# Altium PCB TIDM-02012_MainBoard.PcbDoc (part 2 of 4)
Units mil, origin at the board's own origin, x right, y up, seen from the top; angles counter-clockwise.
Board outline 6550 x 5100 mil, 4 copper layers (Top Layer, Layer 1, Layer 2, Bottom Layer), stack 81.2 mil thick; 300 components, 157 nets, 916 pads, 350 vias.
Unrouted connection lines stored in the file: 93.
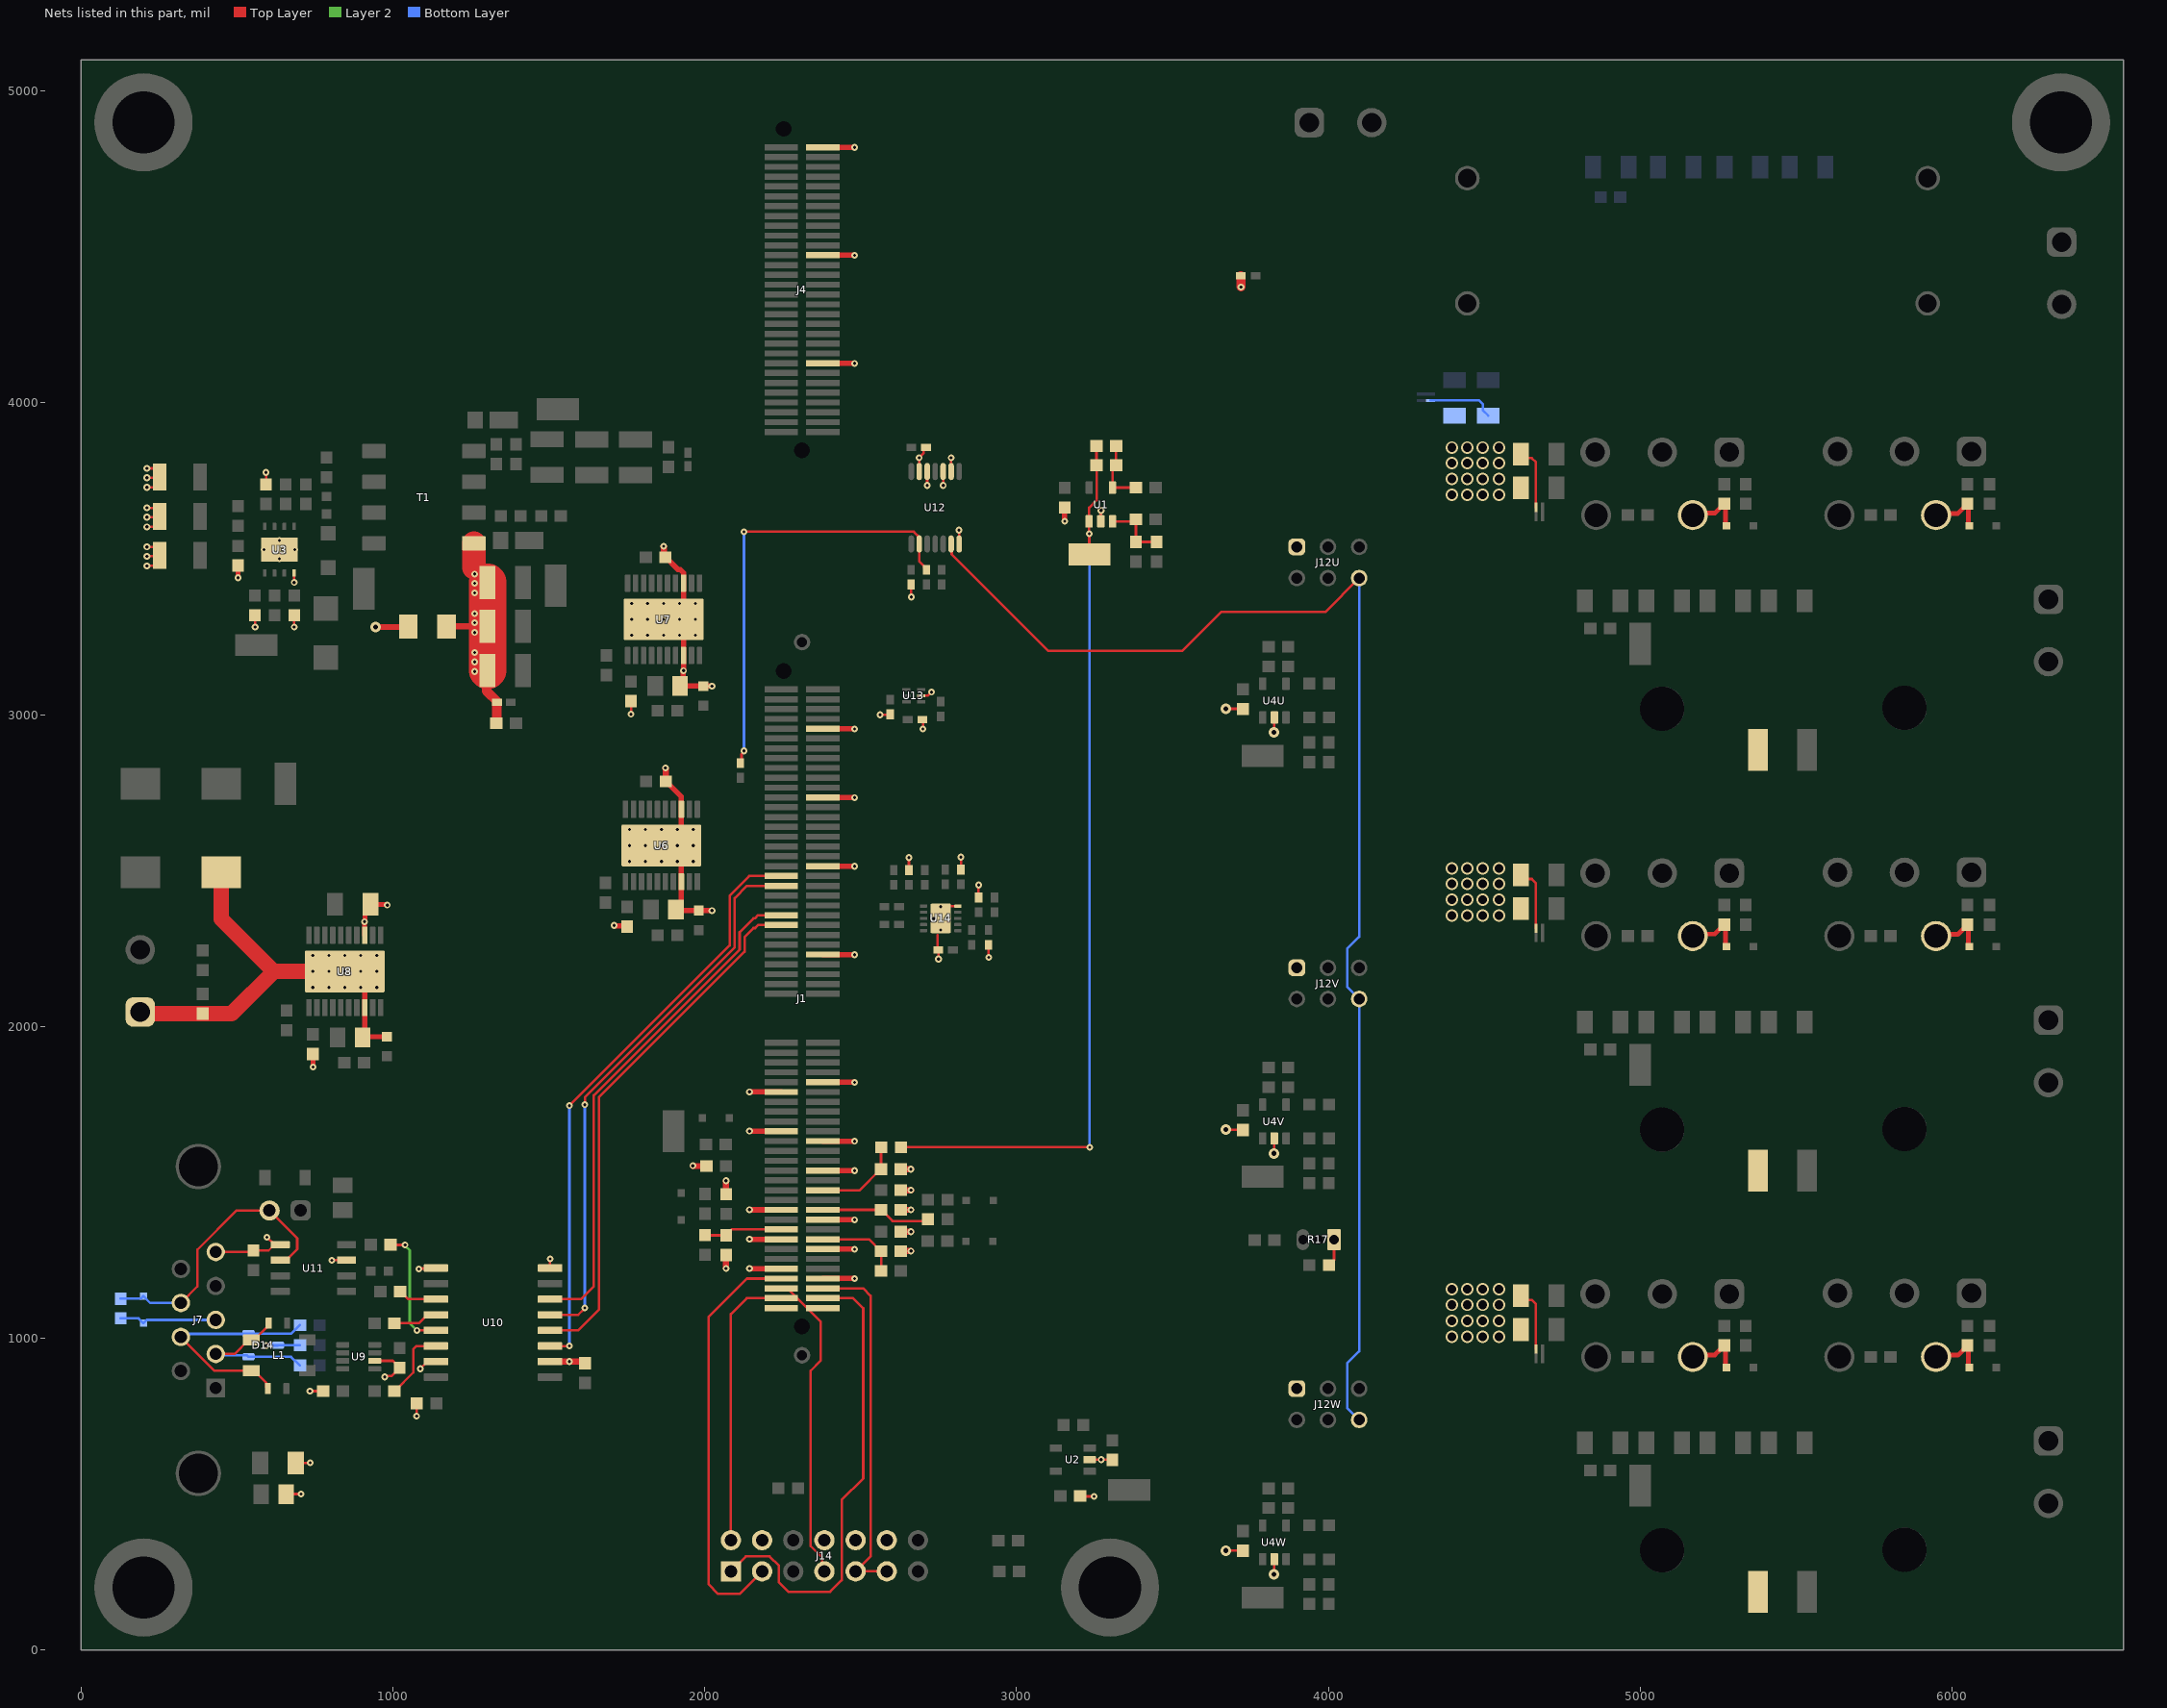
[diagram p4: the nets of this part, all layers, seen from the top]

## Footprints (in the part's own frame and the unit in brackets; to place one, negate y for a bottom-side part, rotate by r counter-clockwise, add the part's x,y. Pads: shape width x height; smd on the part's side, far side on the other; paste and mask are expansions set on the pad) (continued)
Wurth_691311500102 [mm] "Terminal Block, 2 Pos, 5.08mm, TH"
  rrect50% 2.4x2.4 hole 1.6: 1(-2.54,0)
  round 2.4 hole 1.6: 2(2.54,0)
  body extent -6.08,-3.8 6.08,4.7, height 12

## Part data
C1 C4 C18U C18V C18W C21U C21V C21W: library part CMP-0085572-1, "CAP, CERM, 47 pF, 100 V,+/- 5%, C0G/NP0, AEC-Q200 Grade 1, 0603", Cap_Case=0603, Manufacturer=Kemet, TempCo=C0G/NP0, Tolerance_%=5%, Value2=100V, ValueDisplayed=47pF
C2 C3 C11 C20U C20V C20W C28 C31 C42 C46: library part CMP-0006861-4, "CAP, CERM, 0.1 uF, 50 V, +/- 10%, X7R, 0603", Cap_Case=0603, Manufacturer=Kemet, Supplier Part Number 1=399-5089-1-ND, TempCo=X7R, Tolerance_%=10%, Value1=Unknown, Value2=50V, ValueDisplayed=0.1uF
C5 C19U C19V C19W: library part CMP-0085252-1, "CAP, CERM, 0.047 µF, 50 V,+/- 5%, X7R, 0603", Cap_Case=0603, Manufacturer=AVX, TempCo=X7R, Tolerance_%=5%, Value2=50V, ValueDisplayed=0.047µF
C6: library part CMP-0012359-3, "CAP, Film, 10 uF, 1300 V, +/- 10%, 0.0065 ohm, AEC-Q200 Grade 2, TH", Cap_Case=42x28x37mm, Manufacturer=TDK, Supplier Part Number 1=B32776G1106K-ND, Tolerance_%=10%, Value1="0.0065 ohm", Value2=1300V, ValueDisplayed=10uF
C7 C38U C38V C38W: library part CMP-0007221-4, "CAP, CERM, 470 pF, 50 V, +/- 5%, C0G/NP0, 0603", Cap_Case=0603, Manufacturer=MuRata, Supplier Part Number 1=490-1443-1-ND, TempCo=C0G/NP0, Tolerance_%=5%, Value1=Unknown, Value2=50V, ValueDisplayed=470pF
C8U C8V C8W: library part CMP-0009325-2, "CAP, CERM, 0.047 uF, 1000 V, +/- 10%, X7R, 1812", Cap_Case=1812, Manufacturer=Kemet, Supplier Part Number 1=399-6494-1-ND, TempCo=X7R, Tolerance_%=10%, Value1=Unknown, Value2=1000V, ValueDisplayed=0.047uF
C12 C32 C33: library part CMP-0007255-4, "CAP, CERM, 22 pF, 100 V, +/- 5%, C0G/NP0, 0603", Cap_Case=0603, Manufacturer=MuRata, Supplier Part Number 1=490-1335-1-ND, TempCo=C0G/NP0, Tolerance_%=5%, Value1=Unknown, Value2=100V, ValueDisplayed=22pF
C13 C14 C37: library part CMP-0009164-2, "CAP, CERM, 10 uF, 50 V, +/- 10%, X7S, AEC-Q200 Grade 1, 1210", Cap_Case=1210_280, Manufacturer=TDK, Supplier Part Number 1=445-7004-1-ND, TempCo=X7S, Tolerance_%=10%, Value1="0.002827 ohm", Value2=50V, ValueDisplayed=10uF
C15 C16 C17 C23 C24 C29: library part CMP-0080552-1, "CAP, CERM, 22 µF, 25 V,+/- 10%, X7R, AEC-Q200 Grade 1, 1210", Cap_Case=1210, Manufacturer="Taiyo Yuden", Supplier Part Number 1=587-5949-1-ND, TempCo=X7R, Tolerance_%=10%, Value2=25V, ValueDisplayed=22µF
C22 C30: library part CMP-0079602-1, "CAP, CERM, 0.1 µF, 50 V,+/- 10%, X7R, AEC-Q200 Grade 1, 0603", Cap_Case=0603, Manufacturer=Kemet, Supplier Part Number 1=399-6856-1-ND, TempCo=X7R, Tolerance_%=10%, Value2=50V, ValueDisplayed=0.1µF
C25 C40: library part CMP-0082113-1, "CAP, CERM, 1 µF, 25 V,+/- 20%, X7R, AEC-Q200 Grade 1, 0603", Cap_Case=0603, Manufacturer=TDK, Supplier Part Number 1=445-12548-2-ND, TempCo=X7R, Tolerance_%=20%, Value2=25V, ValueDisplayed=1µF
C26 C41 C45: library part CMP-0008003-2, "CAP, CERM, 10 uF, 16 V, +/- 20%, X7R, 0805", Cap_Case=0805, Manufacturer="Taiyo Yuden", Supplier Part Number 1=587-3319-1-ND, TempCo=X7R, Tolerance_%=20%, Value1=Unknown, Value2=16V, ValueDisplayed=10uF
C27 C34: library part CMP-0007079-4, "CAP, CERM, 0.047 uF, 50 V, +/- 10%, X7R, AEC-Q200 Grade 1, 0603", Cap_Case=0603, Manufacturer=TDK, Supplier Part Number 1=445-5664-1-ND, TempCo=X7R, Tolerance_%=10%, Value1="0.049007 ohm", Value2=50V, ValueDisplayed=0.047uF
C35: library part CMP-0008572-2, "CAP, CERM, 1000 pF, 2000 V, +/- 10%, X7R, 1206_190", Cap_Case=1206, Manufacturer="Johanson Technology", TempCo=X7R, Tolerance_%=10%, Value1=Unknown, Value2=2000V, ValueDisplayed=1000pF
C36: library part CMP-0007141-3, "CAP, CERM, 0.047 uF, 25 V, +/- 10%, X7R, AEC-Q200 Grade 1, 0603", Cap_Case=0603, Manufacturer=MuRata, Supplier Part Number 1=490-8018-1-ND, TempCo=X7R, Tolerance_%=10%, Value1=Unknown, Value2=25V, ValueDisplayed=0.047uF
C39U C39V C39W C43: library part CMP-0007197-4, "CAP, CERM, 220 pF, 50 V, +/- 5%, C0G/NP0, 0603", Cap_Case=0603, Manufacturer=MuRata, Supplier Part Number 1=490-1435-1-ND, TempCo=C0G/NP0, Tolerance_%=5%, Value1=Unknown, Value2=50V, ValueDisplayed=220pF
C44: library part CMP-0008821-2, "CAP, CERM, 10 uF, 35 V, +/- 10%, X7R, 1206", Cap_Case=1206, Manufacturer="Taiyo Yuden", Supplier Part Number 1=587-3007-1-ND, TempCo=X7R, Tolerance_%=10%, Value1=Unknown, Value2=35V, ValueDisplayed=10uF
C47 C49 C50 C51: library part CMP-0006857-4, "CAP, CERM, 0.1 uF, 16 V, +/- 5%, X7R, 0603", Cap_Case=0603, Manufacturer=Kemet, Supplier Part Number 1=399-1097-1-ND, TempCo=X7R, Tolerance_%=5%, Value1=Unknown, Value2=16V, ValueDisplayed=0.1uF
C48: library part CMP-0007088-4, "CAP, CERM, 4700 pF, 100 V, +/- 10%, X7R, AEC-Q200 Grade 1, 0603", Cap_Case=0603, Manufacturer=TDK, Supplier Part Number 1=445-5810-1-ND, TempCo=X7R, Tolerance_%=10%, Value1="0.469862 ohm", Value2=100V, ValueDisplayed=4700pF
C52: library part CMP-0006777-4, "CAP, CERM, 220 pF, 50 V, +/- 5%, C0G/NP0, 0603", Cap_Case=0603, Manufacturer=AVX, Supplier Part Number 1=478-1179-1-ND, TempCo=C0G/NP0, Tolerance_%=5%, Value1="0.083 ohm", Value2=50V, ValueDisplayed=220pF
C53: library part CMP-0008484-2, "CAP, CERM, 0.01 uF, 100 V, +/- 5%, X7R, 1206", Cap_Case=1206, Manufacturer=AVX, Supplier Part Number 1=478-3783-1-ND, TempCo=X7R, Tolerance_%=5%, Value1="0.119 ohm", Value2=100V, ValueDisplayed=0.01uF
C54 C55 C56 C57 C58: library part CMP-0080702-1, "CAP, CERM, 0.1 µF, 16 V,+/- 5%, X7R, AEC-Q200 Grade 1, 0402", Cap_Case=0402, Manufacturer=MuRata, Supplier Part Number 1=490-16433-1-ND, TempCo=X7R, Tolerance_%=5%, Value2=16V, ValueDisplayed=0.1µF
C59: library part CMP-0080610-1, "CAP, CERM, 0.1 µF, 25 V,+/- 10%, X7R, AEC-Q200 Grade 1, 0402", Cap_Case=0402, Manufacturer=TDK, Supplier Part Number 1=445-6902-1-ND, TempCo=X7R, Tolerance_%=10%, Value2=25V, ValueDisplayed=0.1µF
D1 D7U D7V D7W: library part CMP-0028792-2, "Diode, Schottky, 40 V, 0.52 A, AEC-Q101, SOD-323", Manufacturer="Diodes Inc.", Value1=0.52A, Value2=V
D2U D2V D2W D5U D5V D5W: library part CMP-0028748-2, "Diode, Schottky, 40 V, 0.5 A, SOD-323", Manufacturer=Toshiba, Value1=0.5A, Value2=0.6V
D3 D10: library part CMP-0028825-2, "Diode, Schottky, 60 V, 3 A, AEC-Q101, SOD-123HE", Manufacturer="Fairchild Semiconductor", Value1=3A, Value2=0.65V
D4: library part CMP-0005882-5, "Diode, Zener, 18 V, 300 mW, SOD-523", Manufacturer="Diodes Inc.", Power_W=300mW, Value1=0.3W
D6: library part CMP-0005514-4, "Diode, Zener, 27 V, 3 W, SMA", Manufacturer="Micro Commercial Components", Power_W=3W
D8: library part CMP-0005904-4, "Diode, Zener, 8.2 V, 300 mW, SOD-523", Manufacturer="Diodes Inc.", Power_W=300mW, Value1=0.3W
D9: library part CMP-0077075-2, "Diode, Schottky, 100 V, 3 A, AEC-Q101, SMC", Manufacturer=Vishay-Siliconix, Value1=3A, Value2=0.8V
D11: library part CMP-0005729-4, "Diode, TVS, Uni, 26 V, 42.1 Vc, AEC-Q101, SMC", Manufacturer=Littelfuse, Value1=3000W
D12 D13 D17: library part CMP-0002892-3, "LED, Yellow, SMD", Color=yellow, Manufacturer="Wurth Elektronik", Value1=W, Value2=2V
D14: library part CMP-0005919-3, "Diode, TVS, Bi, 24 V, SOT-23", Manufacturer="ON Semiconductor", Value1=350W
D15: library part CMP-0076974-2, "Diode, Switching, 100 V, 0.15 A, SOD-123", Manufacturer="Micro Commercial Components", Value1=0.15A, Value2=1.25V
D16: library part CMP-0005821-3, "Diode, TVS, Bi, 15 V, SOD-323", Manufacturer="NXP Semiconductor", Value1=160W
D18: library part CMP-0085903-1, "Diode, Schottky, 60 V, 3 A, AEC-Q101, SOD-123W", Manufacturer=Nexperia, Value1=3A, Value2=0.62V
H1 H2 H3 H4: library part CMP-0003617-1, "Machine Screw, Round, #4-40 x 1/4, Nylon, Philips panhead", Manufacturer="B&F Fastener Supply", Supplier Part Number 1=H542-ND
H5 H6 H7 H8: library part CMP-0003610-1, "Standoff, Hex, 0.5\"L #4-40 Nylon", Manufacturer=Keystone, Supplier Part Number 1=36-1902C-ND
"High Voltage1" "High Voltage2": library part CMP-0074835-1, "IEC 61010-1 High Voltage Warning"
J1: library part CMP-0003814-2, "C2000 controlCARD-120HSEC connector, SMT", Manufacturer=Samtec
J2 J3 J5 J13U J13V J13W: library part CMP-0084907-1, "Terminal Block, 2 Pos, 5.08mm, Tin, TH", Color=Green, Current_A=20A, Manufacturer="Wurth Elektronik", Voltage_V=300V
J4: library part CMP-0003859-2, "C2000 controlCARD-180HSEC (60-pin addon) connector, SMT", Manufacturer=Samtec
J6: library part CMP-0075405-3, "Header, 100mil, 2x1, Gold, TH", Color=Black, Current_A=6.3A, Manufacturer=Samtec, Supplier Part Number 1=SAM1029-02-ND, Voltage_V=550V
J7: library part CMP-0054820-2, "Receptacle, D-Sub, 9 Position, R/A, TH", Color=Black, Current_A=3A, Manufacturer="Wurth Elektronik", Supplier Part Number 1=16T0655, Voltage_V=125V
J8U J8V J8W J9U J9V J9W J10U J10V J10W J11U J11V J11W: library part CMP-0055026-1, Manufacturer=Mill-Max, Supplier Part Number 1=0312-015153427100-ND
J12U J12V J12W: library part CMP-0082603-1, "Receptacle, 2.54mm, 3x2, Tin, TH", Color=Green, Manufacturer="TE Connectivity", Supplier Part Number 1=A106656-ND
J14: library part CMP-0054695-2, "Header (shrouded), 100 mil, 7x2, Gold, TH", Manufacturer="Sullins Connector Solutions", Supplier Part Number 1=S9170-ND
L1: library part CMP-0062430-2, "Inductor, Ferrite, 100 uH, 0.15 A, 2 ohm, SMD", Manufacturer=TDK, Supplier Part Number 1=445-3959-1-ND, Value1="2 ohm", Value2=0.15A, ValueDisplayed=100uH
LBL1: library part CMP-0003625-1, "Thermal Transfer Printable Labels, 0.650\" W x 0.200\" H - 10,000 per roll", Manufacturer=Brady, Supplier Part Number 1=97C5133
Logo1: library part CMP-0074838-1, "Texas Instrument Corporate Signature"
Logo2: library part CMP-0074844-1
Logo3: library part CMP-0074847-1, "FCC_disclaimer"
Logo4: library part CMP-0074769-1
NT1 NT2 NT3U NT3V NT3W NT4U NT4V NT4W: library part CMP-0078142-4, "Single point connection between nets.", Manufacturer=N/A
Q1U Q1V Q1W Q2U Q2V Q2W: library part CMP-0000526-4, "Transistor, IGBT, 1200 V, 50 A, TO-247", Manufacturer="Infineon Technologies", Value1="50 A"
R1 R2 R24U R24V R24W R25U R25V R25W: library part CMP-0018570-2, "RES, 0.01, 1%, 1 W, 1206", Manufacturer=Vishay-Dale, Power_W=1W, Supplier Part Number 1=WSLP-.01CT-ND, TempCo="75 ppm/C", Tolerance_%=1%, Value_Code=R010, ValueDisplayed=0.01
R3 R5 R10 R12 R14 R16U R16V R16W R23U R23V R23W R29U R29V R29W R33U R33V R33W R41 R46 R48 R57: library part CMP-0022746-5, "RES, 10.0 k, 1%, 0.1 W, 0603", Manufacturer=Yageo, Power_W=100mW, Supplier Part Number 1=311-10.0KHRCT-ND, TempCo="100 ppm/C", Tolerance_%=1%, Value2=0.1W, Value_Code=10k0, ValueDisplayed=10.0k
R4 R9 R31U R31V R31W R32U R32V R32W: library part CMP-0022895-5, "RES, 1.00 k, 1%, 0.1 W, 0603", Manufacturer=Yageo, Power_W=100mW, Supplier Part Number 1=311-1.00KHRCT-ND, TempCo="100 ppm/C", Tolerance_%=1%, Value2=0.1W, Value_Code=1k00, ValueDisplayed=1.00k
R6 R7 R8 R26U R26V R26W R27U R27V R27W R28U R28V R28W: library part CMP-0017631-3, "RES, 499 k, 1%, 0.25 W, AEC-Q200 Grade 0, 1206", Manufacturer=Panasonic, Power_W=250mW, Supplier Part Number 1=P499KFCT-ND, TempCo="100 ppm/C", Tolerance_%=1%, Value2=0.25W, Value_Code=499k
R11 R30U R30V R30W: library part CMP-0017634-3, "RES, 5.11 k, 1%, 0.25 W, AEC-Q200 Grade 0, 1206", Manufacturer=Panasonic, Power_W=250mW, Supplier Part Number 1=P5.11KFCT-ND, TempCo="100 ppm/C", Tolerance_%=1%, Value2=0.25W, Value_Code=5k11, ValueDisplayed=5.11k
R13U R13V R13W R20U R20V R20W: library part CMP-0022170-4, "RES, 1.00, 1%, 0.1 W, AEC-Q200 Grade 0, 0603", Manufacturer=Vishay-Dale, Power_W=100mW, Supplier Part Number 1=52K8059, TempCo="100 ppm/C", Tolerance_%=1%, Value2=0.1W, Value_Code=1R00, ValueDisplayed=1.00
R15U R15V R15W R22U R22V R22W: library part CMP-0023206-5, "RES, 5.11, 1%, 0.1 W, 0603", Manufacturer=Yageo, Power_W=100mW, Supplier Part Number 1=311-5.11HRCT-ND, TempCo="200 ppm/C", Tolerance_%=1%, Value2=0.1W, Value_Code=5R11, ValueDisplayed=5.11
R17: library part CMP-0088739-1, "PTC Thermistor 10 kOhms TO-226-2, TO-92-2 (TO-226AC) Short Body", Digikey Part Number=296-TMP6131QLPGMQ1CT-ND, Manufacturer="Texas Instruments", Mouser Part Number=595-TMP6131QLPGMQ1, Operating Temperature Range="-40°C to +125°C", TempCo=6400ppm/°C, Tolerance_%=1%
R18 R21: library part CMP-0084243-1, "RES, 100, 1%, 0.25 W, AEC-Q200 Grade 0, 0603", Manufacturer=Vishay-Dale, Power_W=250mW, TempCo="100 ppm/C", Tolerance_%=1%, Value2=0.25W, Value_Code=100R, ValueDisplayed=100
R19: library part CMP-0021991-4, "RES, 100, 1%, 0.1 W, AEC-Q200 Grade 0, 0603", Manufacturer=Vishay-Dale, Power_W=100mW, Supplier Part Number 1=541-100HCT-ND, TempCo="100 ppm/C", Tolerance_%=1%, Value2=0.1W, Value_Code=100R, ValueDisplayed=100
R34: library part CMP-0022841-5, "RES, 17.8 k, 1%, 0.1 W, 0603", Manufacturer=Yageo, Power_W=100mW, Supplier Part Number 1=311-17.8KHRCT-ND, TempCo="100 ppm/C", Tolerance_%=1%, Value2=0.1W, Value_Code=17k8, ValueDisplayed=17.8k
R35: library part CMP-0023028-4, "RES, 324 k, 1%, 0.1 W, 0603", Manufacturer=Yageo, Power_W=100mW, Supplier Part Number 1=311-324KHRCT-ND, TempCo="100 ppm/C", Tolerance_%=1%, Value2=0.1W, Value_Code=324k
R36: library part CMP-0023216-5, "RES, 61.9 k, 1%, 0.1 W, 0603", Manufacturer=Yageo, Power_W=100mW, Supplier Part Number 1=311-61.9KHRCT-ND, TempCo="100 ppm/C", Tolerance_%=1%, Value2=0.1W, Value_Code=61k9, ValueDisplayed=61.9k
R37: library part CMP-0023077-5, "RES, 3.09 k, 1%, 0.1 W, 0603", Manufacturer=Yageo, Power_W=100mW, Supplier Part Number 1=311-3.09KHRCT-ND, TempCo="100 ppm/C", Tolerance_%=1%, Value2=0.1W, Value_Code=3k09, ValueDisplayed=3.09k
R38: library part CMP-0023202-5, "RES, 5.62 k, 1%, 0.1 W, 0603", Manufacturer=Yageo, Power_W=100mW, Supplier Part Number 1=311-5.62KHRCT-ND, TempCo="100 ppm/C", Tolerance_%=1%, Value2=0.1W, Value_Code=5k62, ValueDisplayed=5.62k
R39: library part CMP-0022030-4, "RES, 12.1 k, 1%, 0.1 W, AEC-Q200 Grade 0, 0603", Manufacturer=Vishay-Dale, Power_W=100mW, Supplier Part Number 1=541-12.1KHCT-ND, TempCo="100 ppm/C", Tolerance_%=1%, Value2=0.1W, Value_Code=12k1, ValueDisplayed=12.1k
R40 R43U R43V R43W: library part CMP-0023168-5, "RES, 51.1, 1%, 0.1 W, 0603", Manufacturer=Yageo, Power_W=100mW, Supplier Part Number 1=311-51.1HRCT-ND, TempCo="100 ppm/C", Tolerance_%=1%, Value2=0.1W, Value_Code=51R1, ValueDisplayed=51.1
R42 R47 R74: library part CMP-0023013-5, "RES, 300, 1%, 0.1 W, 0603", Manufacturer=Yageo, Power_W=100mW, Supplier Part Number 1=311-300HRCT-ND, TempCo="100 ppm/C", Tolerance_%=1%, Value2=0.1W, Value_Code=300R, ValueDisplayed=300
R44 R64 R66 R67 R73 R79: library part CMP-0026992-3, "RES, 0, 5%, 0.1 W, AEC-Q200 Grade 0, 0402", Manufacturer=Panasonic, Power_W=100mW, Supplier Part Number 1=P0.0JCT-ND, TempCo="600 ppm/C", Tolerance_%=5%, Value2=0.1W, Value_Code=0000, ValueDisplayed=0
R45U R45V R45W R75: library part CMP-0022928-4, "RES, 22.0, 1%, 0.1 W, 0603", Manufacturer=Yageo, Power_W=100mW, Supplier Part Number 1=311-22.0HRCT-ND, TempCo="100 ppm/C", Tolerance_%=1%, Value2=0.1W, Value_Code=22R0, ValueDisplayed=22.0
R49 R54: library part CMP-0093667-1, "CRCW Thick Film Commodity Chip Resistor Jumper 0603 Size 0 Ohm 0.1 W 2-Pin SMD Paper T/R", Digikey Part Number=541-4013-1-ND, Manufacturer=Vishay, Mouser Part Number=71-CRCW06030000Z0EBC, Operating Temperature Range="-55°C to +155°C", Power_W=100mW
R50 R52: library part CMP-0023213-5, "RES, 60.4, 1%, 0.1 W, 0603", Manufacturer=Yageo, Power_W=100mW, Supplier Part Number 1=311-60.4HRCT-ND, TempCo="100 ppm/C", Tolerance_%=1%, Value2=0.1W, Value_Code=60R4, ValueDisplayed=60.4
R51 R53 R58 R59: library part CMP-0022926-4, "RES, 22.1, 1%, 0.1 W, 0603", Manufacturer=Yageo, Power_W=100mW, Supplier Part Number 1=311-22.1HRCT-ND, TempCo="100 ppm/C", Tolerance_%=1%, Value2=0.1W, Value_Code=22R1, ValueDisplayed=22.1
R55: library part CMP-0023343-3, "RES, 0, 1%, 0.1 W, AEC-Q200 Grade 0, 0603", Manufacturer="Stackpole Electronics Inc", Power_W=100mW, Supplier Part Number 1=RMCF0603ZT0R00CT-ND, TempCo=ppm/C, Tolerance_%=1%, Value2=0.1W, Value_Code=0
R56: library part CMP-0021519-3, "RES, 1.00 k, 1%, 0.125 W, AEC-Q200 Grade 0, 0805", Manufacturer=Panasonic, Power_W=125mW, Supplier Part Number 1=P1.00KCCT-ND, TempCo="100 ppm/C", Tolerance_%=1%, Value2=0.125W, Value_Code=1k00, ValueDisplayed=1.00k
R60: library part CMP-0021522-3, "RES, 1.00 M, 1%, 0.125 W, AEC-Q200 Grade 0, 0805", Manufacturer=Panasonic, Power_W=125mW, Supplier Part Number 1=P1.00MCCT-ND, TempCo="100 ppm/C", Tolerance_%=1%, Value2=0.125W, Value_Code=1M00, ValueDisplayed=1.00M
R61 R62 R63 R65 R68 R69 R70 R71 R72: library part CMP-0078779-1, "RES, 10.0 k, 1%, 0.2 W, AEC-Q200 Grade 0, 0402", Manufacturer=Panasonic, Power_W=200mW, Supplier Part Number 1=P17230CT-ND, TempCo="100 ppm/C", Tolerance_%=1%, Value2=0.2W, Value_Code=10k0, ValueDisplayed=10.0k
R76: library part CMP-0022679-3, "RES, 100, 1%, 0.1 W, AEC-Q200 Grade 0, 0603", Manufacturer=Panasonic, Power_W=100mW, Supplier Part Number 1=P100HCT-ND, TempCo="100 ppm/C", Tolerance_%=1%, Value2=0.1W, Value_Code=100R, ValueDisplayed=100
R77 R78: library part CMP-0023153-5, "RES, 4.70 k, 1%, 0.1 W, 0603", Manufacturer=Yageo, Power_W=100mW, Supplier Part Number 1=311-4.70KHRCT-ND, TempCo="100 ppm/C", Tolerance_%=1%, Value2=0.1W, Value_Code=4k70, ValueDisplayed=4.70k
T1: library part CMP-0094165-1, "Bobbin Packages EP7 8-Terminal, SMT, Horizonta", Frequency_Fixed=350kHz, Manufacturer="Wurth Electronics", Operating Temperature Range="-40°C to +125°C"
TP1 TP2 TP3 TP4U TP4V TP4W TP5U TP5V TP5W TP7 TP8 TP10: library part CMP-0055152-1, "Test Point, Miniature, SMT", Manufacturer=Keystone, Supplier Part Number 1=36-5015TR-ND
TP6 TP9: library part CMP-0055152-1, "Test Point, Miniature, SMT", Manufacturer=Keystone, PartNumber=5015, Supplier Part Number 1=36-5015TR-ND
U1 U4U U4V U4W: library part CMP-0861047-2, "50-MHz, Low-Power, Gain of 6-V/V Stable, Rail-to-Rail Output CMOS Operational Amplifier, DBV0005A (SOT-23-5)", Alternate Manufacturer="Texas Instruments"
U2: library part CMP-0073534-1, "3-MHz, Low-Power, Internal EMI Filter, RRIO, Operational Amplifier, DBV0005A (SOT-23-5)", Alternate Manufacturer="Texas Instruments", Alternate PartNumber=TLV314QDBVTQ1
U3: library part CMP-0860959-2, "42-VIN PSR Flyback DC/DC Converter with 65-V, 4-A Integrated MOSFET, NGU0008C (WSON-8)", Alternate Manufacturer="Texas Instruments"
U6: library part CMP-0085806-1, "Automotive 450mA High-Voltage Ultra-Low-Iq Low-Dropout Regulator, PWP0020D (HTSSOP-20)", Alternate Manufacturer="Texas Instruments", Operating Temperature Range="-40 to 125 C", Rating=Automotive
U7 U8: library part CMP-0085807-1, "Automotive 450mA High-Voltage Ultra-Low-Iq Low-Dropout Regulator, PWP0020D (HTSSOP-20)", Alternate Manufacturer="Texas Instruments", Operating Temperature Range="-40 to 125 C", Rating=Automotive
U9: library part CMP-0089901-1, "Automotive High Speed CAN Transceiver", Manufacturer="Texas Instruments", Max Supply Voltage=5.5V, Min Supply Voltage=4.5V, Nominal Supply Current=5-180mA, Operating Temperature Range="-40°C to +150°C"
U10: library part CMP-0093723-1, "General-Purpose Reinforced Quad-Channel Automotive Digital Isolators with Robust EMC", Digikey Part Number=296-ISO6742QDWRQ1CT-ND, Manufacturer="Texas Instruments", Max Supply Voltage=5.5V, Min Supply Voltage=1.71V, Mouser Part Number=595-ISO6742QDWRQ1, Operating Temperature Range="-40°C to +125°C"
U11: library part CMP-0091357-1, "Fault-Protected LIN Transceiver with Inhibit and Wake", Manufacturer="Texas Instruments", Max Supply Voltage=36V, Min Supply Voltage=4.5V, Nominal Supply Current=300-1200uA, Operating Temperature Range="-40°C to +125°C"
U12: library part CMP-0054468-2, "Automotive Catalog Dual 4-Input Positive-AND Gates, PW0014A, LARGE T&R", F @ Nom Voltage(Max)(Mhz)=70, Generic Part Number=SN74HC21-Q1, ICC @ Nom Voltage(Max)(mA)=0.02, Manufacturer="Texas Instruments", Operating Temperature Range(C)="-40 to 125", Rating=Automotive, tpd @ Nom Voltage(Max)(ns)=140, Voltage(Nom)(V)=5
U13: library part CMP-0750051-1, "Overvoltage and Undervoltage Reset IC With Time Delay and Manual Reset, DSE0006A (WSON-6)", Alternate Manufacturer="Texas Instruments"
U14: library part CMP-0081428-2, "Automotive Precision Voltage Supervisor With Programmable Window Watchdog Timer, DRC0010R (VSON-10)", Alternate Manufacturer="Texas Instruments", Operating Temperature Range="-40 to 125 C", Rating=Automotive
ZZ1: library part CMP-0003616-3
ZZ2: library part CMP-0077236-1
ZZ3: library part CMP-0077237-1
ZZ4: library part CMP-0077238-1

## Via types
v1: diameter 22, hole 10, Top Layer to Bottom Layer, tented both sides, 245 vias
v2: diameter 40, hole 28, Top Layer to Bottom Layer, tented both sides, 60 vias
v3: diameter 34, hole 16, Top Layer to Bottom Layer, tented both sides, 22 vias
v4: diameter 22, hole 10, Top Layer to Bottom Layer, 9 vias
v5: diameter 50, hole 28, Top Layer to Bottom Layer, tented both sides, 9 vias
v6: diameter 40, hole 25, Top Layer to Bottom Layer, tented both sides, 5 vias

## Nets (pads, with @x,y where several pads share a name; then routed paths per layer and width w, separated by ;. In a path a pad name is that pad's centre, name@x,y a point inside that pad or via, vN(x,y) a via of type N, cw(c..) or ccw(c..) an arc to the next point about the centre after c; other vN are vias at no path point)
CAN_H: D14.2 J7.7 L1.4 R52.1 R54.2 | length 754.3
  Top Layer w8: J7.7@320,1003.95 320,1002.5 426.5,896 L1.4@546,896 554.86,896 593.2,857.66 593.2,844.06 R54.2@599.04,838.21
  Bottom Layer w8: J7.7@320,1003.95 329.77,1013.71 535.71,1013.71 D14.2@537,1015 674.02,1015 701.02,1042 R52.1@702,1042
CAN_L: D14.1 J7.2 L1.3 R49.2 R50.2 | length 500.6
  Top Layer w8: J7.2@431.81,949.42 492.13,949.42 537.14,994.43 L1.3@546,994.43 554.86,994.43 594.93,1034.5 595.67,1034.5 601.51,1040.34 R49.2@601.51,1048.21
  Bottom Layer w8: J7.2@431.81,949.42 436.42,944.81 532.39,944.81 D14.1@537,940.2 673.67,940.2 701.02,912.85 R50.2@702,912.85
CAN_RX: R53.1 U10.12 | length 144.3
  Top Layer w8: R53.1@1004.74,1048.21 1083.58,1048.21 1110.37,1075 U10.12@1137.93,1075
CAN_TX: R51.1 U10.14 | length 237.7
  Top Layer w8: R51.1@1004.5,830 1005.48,830 1065,889.52 1065,965.06 1074.94,975 U10.14@1137.93,975
DC-U: C8U.2 C8V.2 C8W.2 NT1.1 NT4U.1 NT4V.1 NT4W.1 R1.2 R2.2 R24U.1 R24V.1 R24W.1 R25U.1 R25V.1 R25W.1 | length 828.3
  Top Layer w8: R24W.1@4617.69,1135.93 4630.84,1122.77 4652.81,1122.77 4666,1109.58 NT4W.1@4666,965 ; R24V.1@4617.69,2485.93 4630.84,2472.77 4652.81,2472.77 4666,2459.58 NT4V.1@4666,2315 ; R24U.1@4617.69,3835.93 4630.84,3822.77 4652.81,3822.77 4666,3809.58 NT4U.1@4666,3665
  Bottom Layer w8: NT1.1@4328,4007.74 4484.07,4007.74 4495.5,3996.31 4495.5,3976.43 R2.2@4513.02,3958.91
  other v2: 4396,1005 4445.75,1005 4495.5,1005 4547.5,1005 4396,1056 4445.75,1056 4495.5,1056 4547.5,1056 4396,1107 4445.75,1107 4495.5,1107 4547.5,1107 4396,1157 4445.75,1157 4495.5,1157 4547.5,1157 4396,2355 4445.75,2355 4495.5,2355 4547.5,2355 4396,2406 4445.75,2406 4495.5,2406 4547.5,2406 4396,2457 4445.75,2457 4495.5,2457 4547.5,2457 4396,2507 4445.75,2507 4495.5,2507 4547.5,2507 4396,3705 4445.75,3705 4495.5,3705 4547.5,3705 4396,3756 4445.75,3756 4495.5,3756 4547.5,3756 4396,3807 4445.75,3807 4495.5,3807 4547.5,3807 4396,3857 4445.75,3857 4495.5,3857 4547.5,3857
EMU0: J1.2
EMU1: J1.1
EN_DRV: J12U.6 J12V.6 J12W.6 U12.6 | length 4365.5
  Top Layer w8: U12.6@2790.37,3547.46 2792.23,3545.61 2792.23,3513.87 3101.28,3204.83 3531.87,3204.83 3656.13,3329.09 3990.09,3329.09 J12U.6@4099,3438 ; J12U.6@4088.5,3448.5 J12U.6@4099,3459
  Bottom Layer w8: J12W.6@4099,738 4060.43,776.57 4060.43,919.32 4099,957.9 J12V.6@4099,2088 4060.43,2126.57 4060.43,2248.92 4099,2287.5 J12U.6@4099,3438 J12U.6@4099,3459
ERRORSTS: R62.1 R79.2 U12.2 | length 1442.6
  Top Layer w8: R79.2@2114,2844.72 R79.2@2118.24,2848.97 ; R79.2@2118.69,2849.41 R79.2@2118.24,2848.97 ; v1(2126,2884.02) 2126,2880.23 2118.24,2872.47 R79.2@2118.24,2848.97 ; v1(2126,3586.66) 2562.25,3586.66 2562.61,3587.02 2671.06,3587.02 2683.28,3574.8 2683.28,3573.53 2688.01,3568.79 U12.2@2688.01,3547.46 2688.01,3491.79 2711.04,3468.76 R62.1@2711.04,3464.82 R62.1@2703.23,3472.64
  Bottom Layer w8: v1(2126,2884.02) v1(2126,3586.66)
G_1U: D2U.1 J8U.1 R15U.1 | length 189.5
  Top Layer w15: J8U.1@5949,3640 5954.47,3645.47 6019.73,3645.47 6049.76,3675.5 R15U.1@6049.76,3676.48 6052.8,3673.44 6052.8,3608.99 D2U.1@6055.84,3605.95
G_1V: D2V.1 J8V.1 R15V.1 | length 189.5
  Top Layer w15: J8V.1@5949,2290 5954.47,2295.47 6019.73,2295.47 6049.76,2325.5 R15V.1@6049.76,2326.48 6052.8,2323.44 6052.8,2258.99 D2V.1@6055.83,2255.95
G_1W: D2W.1 J8W.1 R15W.1 | length 189.5
  Top Layer w15: J8W.1@5949,940 5954.47,945.47 6019.73,945.47 6049.76,975.5 R15W.1@6049.76,976.48 6052.8,973.44 6052.8,908.99 D2W.1@6055.83,905.95
G_2U: D5U.1 J10U.1 R22U.1 | length 190.1
  Top Layer w15: J10U.1@5169,3640 5175.1,3646.1 5239.73,3646.1 5257.92,3664.3 5258.9,3664.3 5270.1,3675.5 R22U.1@5270.1,3676.48 5273.47,3673.12 5273.47,3609.32 D5U.1@5276.83,3605.95
G_2V: D5V.1 J10V.1 R22V.1 | length 190.1
  Top Layer w15: J10V.1@5169,2290 5175.1,2296.1 5239.73,2296.1 5257.92,2314.3 5258.9,2314.3 5270.1,2325.5 R22V.1@5270.1,2326.48 5273.47,2323.12 5273.47,2259.32 D5V.1@5276.83,2255.95
G_2W: D5W.1 J10W.1 R22W.1 | length 190.1
  Top Layer w15: J10W.1@5169,940 5175.1,946.1 5239.73,946.1 5257.92,964.3 5258.9,964.3 5270.1,975.5 R22W.1@5270.1,976.48 5273.47,973.12 5273.47,909.32 D5W.1@5276.83,905.95
GND: C13.1 C14.1 C28.2 C34.2 C35.2 C36.2 C37.1 C44.2 C45.2 C46.2 C47.2 C48.1 C49.2 C51.2 C52.2 C53.2 D11.2 D14.3 D16.1 D17.1 J5.1 J7.3 J7.5 R38.1 R39.1 R55.1 R60.1 U3.8 U3.9@636,3529.13 U8.8 U8.13 U8.21 U9.2 U10.9 U10.15 U11.3 U11.5 | length 3359
  Top Layer w8: v1(211,3477.11) 249.29,3477.11 C13.1@252.03,3479.85 ; v1(211,3508.11) 249.29,3508.11 C13.1@252.03,3510.85 ; v1(211,3538.11) 249.29,3538.11 C13.1@252.03,3540.85 ; v1(211,3602.31) 249.29,3602.31 C14.1@252.03,3605.05 ; v1(211,3633.31) 249.29,3633.31 C14.1@252.03,3636.05 ; v1(211,3663.31) 249.29,3663.31 C14.1@252.03,3666.05 ; v1(211,3729) 249.29,3729 C37.1@252.03,3731.74 ; v1(211,3760) 249.29,3760 C37.1@252.03,3762.74 ; v1(211,3790) 249.29,3790 C37.1@252.03,3792.74 ; J7.5@431.81,1276.58 548.03,1276.58 C51.2@552.75,1281.3 601.3,1281.3 U11.5@620,1300 ; C36.2@557.34,3319.04 558,3318.38 v1(558,3281) ; C28.2@592.96,3738.52 593,3738.57 v1(593,3777) ; v1(596,1324) U11.5@620,1300 ; U11.5@638.7,1300 U11.5@620,1300 ; R60.1@657.35,499.94 657.41,500 v1(705,500) ; v1(683.24,3281) R39.1@683.24,3319.04 ; v1(683.24,3423.95) U3.8@683.24,3454.33 ; C53.2@688.44,599.5 688.95,600 v1(735,600) ; v1(733.99,830.24) 776.15,830.24 R55.1@776.39,830 ; v1(804.06,1250) U11.3@851.3,1250 ; U9.2@941.75,927.42 999.57,927.42 1021,905.98 C47.2@1021,905 1021,904.02 995.52,878.53 976.63,878.53 v1(973.95,875.85) ; v1(1076,750) 1076,790.5 C49.2@1076.5,791 ; v1(1083.58,1222.06) 1085.06,1223.53 1136.46,1223.53 U10.9@1137.93,1225 ; v1(1088,902) 1088,902.63 1110.37,925 U10.15@1137.93,925
  Top Layer w16: v1(503,3439) 503.17,3439.17 503.17,3478.1 R38.1@503.34,3478.27 ; C46.2@743.26,1911.7 743.63,1911.34 743.63,1870.37 v1(744,1870) ; v1(845.63,2176.28) 850.67,2176.28 909.6,2117.35 U8.8@909.6,2060.14 909.6,1971.25 C45.2@905.57,1967.22 ; C45.2@902.62,1964.27 C45.2@905.57,1967.22 ; U8.13@909.6,2292.42 909.3,2292.72 909.3,2335.7 v1(909,2336) 909,2337.62 910.8,2339.42 910.8,2373.68 C44.2@928.39,2391.27 978.11,2391.27 980.38,2389 v1(982,2389) ; D17.1@980.73,1967.22 C45.2@905.57,1967.22
  Top Layer w20: v3(944,3281) 1047.86,3281 C35.2@1049.8,3282.95
  Top Layer w50: J5.1@190,2046.15 195.14,2041.01 C34.2@389.97,2041.01 482.45,2041.01 617.72,2176.28 ; D11.2@448.97,2494.87 448.97,2345.03 617.72,2176.28 ; v1(743.26,2176.28) 617.72,2176.28
  Bottom Layer w8: C52.2@127.08,1063.58 184.63,1063.58 D16.1@200,1048.21 210.26,1058.47 J7.3@431.81,1058.47 ; v1(593,976) 593.8,976.8 630.69,976.8 D14.3@631.49,977.6 C48.1@702,977.6
  other v1: 743.26,2125.1 794.45,2125.1 845.63,2125.1 896.81,2125.1 947.99,2125.1 794.45,2176.28 896.81,2176.28 947.99,2176.28 743.26,2227.46 794.45,2227.46 845.63,2227.46 896.81,2227.46 947.99,2227.46 636,3500 586.79,3529.13 685.21,3529.13 636,3558.27
GND_MCU: C2.1 C3.1 C7.2 C11.1 C20U.1 C20V.1 C20W.1 C23.1 C24.1 C25.2 C26.2 C29.1 C30.1 C31.2 C35.1 C38U.2 C38V.2 C38W.2 C39U.2 C39V.2 C39W.2 C40.2 C41.2 C42.2 C43.2 C50.2 C54.2 C55.2 C56.2 C57.2 C58.2 C59.2 D8.2 D12.1 D13.1 J1.7 J1.10 J1.13 J1.16 J1.19 J1.22 J1.29 J1.35 J1.38 J1.46 J1.47 J1.65 J1.83 J1.97 J1.111 J4.135 J4.157 J4.179 J12U.1 J12V.1 J12W.1 J14.4 J14.8 J14.10 J14.12 R12.1 R17.1 R44.1 R63.1 R71.1 R72.1 T1.8 U1.2 U2.2 U4U.2 U4V.2 U4W.2 U6.8 U6.13 U6.21 U7.8 U7.13 U7.21 U10.2 U10.8 U12.7 U12.9 U12.10 U12.12 U12.13 U13.5 U14.5 U14.11 | length 5778.8
  Top Layer w8: v1(1262.25,3138.32) 1300.54,3138.32 C29.1@1303.28,3141.06 ; v1(1262.25,3169.32) 1300.54,3169.32 C29.1@1303.28,3172.06 ; v1(1262.25,3199.32) 1300.54,3199.32 1303.28,3202.06 ; v1(1262.25,3263.51) 1300.54,3263.51 C24.1@1303.28,3266.25 ; v1(1262.25,3294.51) 1300.54,3294.51 C24.1@1303.28,3297.25 ; v1(1262.25,3324.51) 1300.54,3324.51 C24.1@1303.28,3327.25 ; v1(1262.25,3390.2) 1300.54,3390.2 C23.1@1303.28,3392.95 ; v1(1262.25,3421.2) 1300.54,3421.2 C23.1@1303.28,3423.95 ; v1(1262.25,3451.2) 1300.54,3451.2 C23.1@1303.28,3453.95 ; U10.8@1504.07,1225 v1(1504.07,1254.17) ; v1(1566,925) 1610.5,925 1610.88,924.62 C50.2@1616,919.5 ; C42.2@1763.61,3043.19 1763.84,3042.96 v1(1763.84,3001.41) ; v1(2562.25,2999.38) 2593.62,2999.38 C54.2@2595,3000.76 ; R72.1@2655.08,2501.36 v1@2655.08,2541.35 ; v1@2662.42,3377.59 R63.1@2662.42,3417.58 ; v1(2687.76,3824.1) 2701.87,3838.21 2701.87,3848.82 C59.2@2709.66,3856.61 ; U12.13@2688.01,3779.75 v1@2688.01,3823.85 ; U13.5@2694.22,3060.8 2715.85,3060.8 v1(2727.44,3072.38) ; C55.2@2698.03,2984.32 2699.94,2982.4 v1(2699.94,2954) ; v1@2713.6,3735.64 U12.12@2713.6,3779.75 ; 2746.97,2292.92 2746.97,2246.81 C56.2@2748.94,2244.84 2749.77,2244.01 v1(2749.77,2215.84) ; U14.11@2756.81,2346.47 2756.81,2357.34 2785.29,2385.82 U14.5@2811.93,2385.84 ; v1@2764.78,3735.64 U12.10@2764.78,3779.75 ; U12.9@2790.37,3779.75 v1@2790.37,3823.85 ; U12.7@2815.96,3547.46 v1@2815.96,3591.57 ; v1(2821.63,2542.84) 2821.7,2542.76 2821.7,2502.78 C58.2@2821.77,2502.7 ; R71.1@2878.34,2413.43 v1@2878.34,2453.42 ; v1@2910.61,2221.8 C57.2@2910.58,2261.82 ; C3.1@3204.13,494.37 3206.19,492.32 v1(3248.84,492.32) ; U2.2@3234.61,610.37 v1(3271.38,610.37) 3306.47,610.37 R12.1@3307.47,609.37 ; U1.2@3270.44,3619.94 3270.44,3654.44 v1(3271,3655) ; v3(3671.84,318.82) 3725.13,318.82 C20W.1@3726,317.95 ; v3(3671.84,1668.82) 3725.13,1668.82 C20V.1@3726,1667.95 ; v3(3671.84,3018.82) 3725.13,3018.82 C20U.1@3726,3017.95 ; v3(3825.84,242.82) 3826.42,243.4 3826.42,290.24 U4W.2@3827,290.82 ; v3(3825.84,1592.82) 3826.42,1593.4 3826.42,1640.24 U4V.2@3827,1640.82 ; v3(3825.84,2942.82) 3826.42,2943.4 3826.42,2990.24 U4U.2@3827,2990.82 ; C11.1@4001.99,1234.48 4002.98,1234.48 4017.68,1249.18 4017.68,1250.16 4018.46,1250.95 R17.1@4018.46,1316.11
  Top Layer w17: v1(1709.7,2324.1) 1710.66,2323.15 1747.59,2323.15 C31.2@1750.73,2320.01 ; C40.2@1868.43,3510.29 1869.41,3510.29 1913.82,3465.89 1920.98,3465.89 1931.79,3455.08 1931.79,3422.06 U7.13@1932.02,3421.83 1932.02,3364.11 1924.77,3356.87 v1(1919.22,3356.87) ; C25.2@1874.94,2785.92 1875.92,2785.92 1924.9,2736.94 1924.9,2696.74 U6.13@1925.13,2696.5 1925.13,2638.79 1917.89,2631.54 v1(1912.34,2631.54) ; v1(1912.34,2529.18) 1917.89,2529.18 1925.13,2521.93 U6.8@1925.13,2464.22 1925.13,2398.48 1907.5,2380.84 C26.2@1907.5,2374.34 1910.29,2371.55 D12.1@1981.14,2371.55 v1(2023.46,2371.55) ; v1(1919.22,3254.5) 1924.77,3254.5 1932.02,3247.26 U7.8@1932.02,3189.54 v1(1932.02,3141.06) 1931.06,3140.1 1931.06,3101.7 C41.2@1921.04,3091.69 D13.1@1995.9,3091.69 v1(2023.46,3091.69) ; v1@2144.1,1222.68 J1.10@2245.14,1222.68 ; v1@2144.1,1317.17 J1.16@2245.14,1317.17 ; v1@2144.1,1411.65 J1.22@2245.14,1411.65 ; v1@2144.1,1663.62 J1.38@2245.14,1663.62 ; v1@2144.1,1789.61 J1.46@2245.14,1789.61 ; J1.7@2379,1191.18 v1@2480.04,1191.18 ; J1.13@2379,1285.67 v1@2480.04,1285.67 ; J1.19@2379,1380.16 v1@2480.04,1380.16 ; J1.29@2379,1537.64 v1@2480.04,1537.64 ; J1.35@2379,1632.13 v1@2480.04,1632.13 ; J1.47@2379,1821.1 v1@2480.04,1821.1 ; J1.65@2379,2230.55 v1@2480.04,2230.55 ; J1.83@2379,2514.02 v1@2480.04,2514.02 ; J1.97@2379,2734.49 v1@2480.04,2734.49 ; J1.111@2379,2954.96 2379.48,2954.48 2480.52,2954.48 v1(2481,2954) ; J4.135@2379,4127.12 v1@2480.04,4127.12 ; J4.157@2379,4473.58 v1@2480.04,4473.58 ; J4.179@2379,4820.04 v1@2480.04,4820.04 ; v1(3154.44,3620) C2.1@3154.44,3664.23
  Top Layer w20: C35.1@1171.85,3282.95 1250.14,3282.95 1261.71,3294.51 v1(1262.25,3294.51) ; U10.2@1504.07,925 v1(1566,925) 1566.38,924.62 C50.2@1610.88,924.62 ; v1(1868.04,3540.01) 1868.43,3539.62 C40.2@1868.43,3510.29 ; v1(1873.95,2828.98) 1873.95,2828.44 1874.94,2827.45 C25.2@1874.94,2785.92 ; v1(1962,1553) 1962.54,1553 1963.54,1552 C43.2@2005.3,1552 ; v1(2068.3,1223.53) C38V.2@2068.3,1266.96 ; C39V.2@2068.3,1461.5 v1(2068.3,1504.93) ; C7.2@2628.5,1542 v1(2661.5,1542) ; C38U.2@2628.7,1279.51 v1(2661.7,1279.51) ; C39U.2@2628.7,1341.5 v1(2661.7,1341.5) ; C38W.2@2628.7,1411.65 v1(2661.7,1411.65) ; C39W.2@2628.7,1474.65 v1(2661.7,1474.65)
  Top Layer w30: C29.1@1303.28,3141.95 1300.87,3139.54 1300.87,3075.12 1334.19,3041.8 D8.2@1334.19,3039.36 1333.44,3038.61 1333.44,2974.62 C30.1@1331.69,2972.87 ; R44.1@3719.4,4407.89 3720,4407.3 v1@3720,4372
  Top Layer w75: T1.8@1259.55,3549.75 1259.65,3549.65 1259.65,3471.32
  Top Layer w120: C29.1@1303.28,3141.95 1303.28,3172.06 1303.28,3202.06 1303.28,3266.25 C24.1@1303.28,3282.95 1303.28,3297.25 1303.28,3327.25 1303.28,3392.95 C23.1@1303.28,3423.95
  other v1: 2480.52,1190.7 2143.62,1223.16 2480.52,1285.19 2143.62,1317.65 2480.52,1379.68 2143.62,1412.13 2480.52,1537.16 2480.52,1631.65 2143.62,1664.1 2143.62,1790.09 2480.52,1820.62 2910.69,2221.72 2480.52,2230.07 2756.81,2309.06 2734.18,2346.47 2779.45,2346.47 2756.81,2383.87 2878.26,2453.49 2480.52,2513.54 1758.8,2529.18 1809.98,2529.18 1861.16,2529.18 1963.52,2529.18 2655.01,2541.42 1758.8,2580.36 1809.98,2580.36 1861.16,2580.36 1912.34,2580.36 1963.52,2580.36 1758.8,2631.54 1809.98,2631.54 1861.16,2631.54 1963.52,2631.54 2480.52,2734.01 1765.68,3254.5 1816.86,3254.5 1868.04,3254.5 1970.41,3254.5 1765.68,3305.69 1816.86,3305.69 1868.04,3305.69 1919.22,3305.69 1970.41,3305.69 1765.68,3356.87 1816.86,3356.87 1868.04,3356.87 1970.41,3356.87 2662.49,3377.52 2815.71,3591.82 2713.84,3735.4 2765.02,3735.4 2790.12,3824.1 2480.52,4126.64 3720,4371.79 2480.52,4473.1 2480.52,4819.56
Ifb_Single: C7.1 J1.25 R40.2 | length 286.3
  Top Layer w8: J1.25@2379,1474.65 2497.17,1474.65 2564.52,1542 C7.1@2565.5,1542 ; C7.1@2566.49,1542 C7.1@2565.5,1542 ; R40.2@2566.5,1612.5 2565.5,1611.5 C7.1@2565.5,1542
Ifb_U: C38U.1 J1.15 R43U.2 | length 265.9
  Top Layer w8: J1.15@2379,1317.17 2527.06,1317.17 2564.72,1279.51 C38U.1@2565.7,1279.51 2565.7,1216.2 R43U.2@2565.5,1216
Ifb_V: C38V.1 J1.18 R43V.2 | length 252.7
  Top Layer w8: R43V.2@2001,1330.5 2001.54,1329.96 C38V.1@2068.3,1329.96 2068.3,1330.94 2086.02,1348.66 J1.18@2245.14,1348.66
Ifb_W: C38W.1 J1.21 R43W.2 | length 354
  Top Layer w8: J1.21@2379,1411.65 C38W.1@2565.7,1411.65 2566.69,1411.65 2602.34,1376 2710.54,1376 R43W.2@2715.95,1381.41
LIN: C52.1 D16.2 J6.2 J7.8 U11.6 | length 911.2
  Top Layer w8: J7.8@320,1113 373,1166 373,1284 498.45,1409.45 J6.2@604.27,1409.45 693,1320.72 693,1285.6 657.4,1250 U11.6@638.7,1250
  Bottom Layer w8: C52.1@127.08,1126.57 191.75,1126.57 D16.2@200,1134.83 221.83,1113 J7.8@320,1113
LIN_RX: J1.74 U10.6 | length 1643
  Top Layer w8: U10.6@1504.07,1125 1603.46,1125 1644.54,1166.09 1644.54,1779.18 2112,2246.64 2112,2302.33 2156.55,2346.88 2161.71,2346.88 2171.36,2356.54 J1.74@2245.14,2356.54
LIN_TX: J1.72 U10.4 | length 1706.1
  Top Layer w8: U10.4@1504.07,1025 1594.25,1025 1660.54,1091.29 1660.54,1772.55 2128,2240.01 2128,2286.83 2156.55,2315.39 2161.71,2315.39 2171.36,2325.04 J1.72@2245.14,2325.04
LINA_RX: R58.1 U10.11 | length 125.6
  Top Layer w8: R58.1@1022.72,1150 1023.7,1150 1048.7,1125 U10.11@1137.93,1125
LINA_TX: R59.1 U10.13 | length 398.1
  Top Layer w8: R59.1@991.94,1300 992.94,1299 v1(1039,1299) ; v1(1077,1025) U10.13@1137.93,1025
  Layer 2 w8: v1(1039,1299) 1039,1296.47 1054,1281.47 1054,1048 v1(1077,1025)
MCAN_RX: J1.80 U10.5 | length 1800.2
  Top Layer w8: U10.5@1504.07,1075 1594.57,1075 1615.25,1095.68 v1(1615.25,1097) ; v1(1615.65,1748.86) 1615.65,1772.91 2096,2253.26 2096,2411.49 2135.53,2451.02 J1.80@2245.14,2451.02
  Bottom Layer w8: v1(1615.25,1097) 1615.25,1748.46 v1(1615.65,1748.86)
MCAN_TX: J1.82 U10.3 | length 1910.6
  Top Layer w8: U10.3@1504.07,975 v1(1566,975) ; v1(1566,1745.89) 2080,2259.89 2080,2419.53 2142.99,2482.52 J1.82@2245.14,2482.52
  Bottom Layer w8: v1(1566,975) v1(1566,1745.89)
MCU_TCK: J1.5 J14.9 J14.11 | length 1166.7
  Top Layer w8: J1.5@2379,1159.68 2508.32,1159.68 2532,1136 2532,300 J14.9@2484,252 J14.11@2584,252
MCU_TDI: J1.8 J14.3 | length 1355.7
  Top Layer w8: J14.3@2184,252 2112,180 2043,180 2012,211 2012,1067.86 2135.32,1191.18 J1.8@2245.14,1191.18
MCU_TDO: J1.6 J14.7 | length 1004
  Top Layer w8: J1.6@2245.14,1159.68 2250.98,1153.84 2271.42,1153.84 2371.87,1053.39 2371.87,927.87 2339.52,895.52 2339.52,333.58 2376.62,296.48 2376.62,259.38 J14.7@2384,252
MCU_TMS: J1.3 J14.1 | length 1512.5
  Top Layer w8: J14.1@2084,252 2132,300 2208.02,300 2238.01,270.01 2238.01,216.5 2268,186.51 2402.51,186.51 2439.52,223.52 2439.52,481.39 2508.32,550.18 2508.32,1095.68 2475.81,1128.19 J1.3@2379,1128.19
MCU_TRSTn: J1.4 J14.2 | length 907.5
  Top Layer w8: J14.2@2084,352 2084,1077.26 2134.93,1128.19 J1.4@2245.14,1128.19
NetC1_1: C1.1 R3.2 R40.1 TP2.1 U1.1 | length 2932.2
  Top Layer w8: R40.1@2629.5,1612.5 v1(3234.61,1612.5) ; TP2.1@3234.44,3513.9 3233.25,3515.1 v1(3233.25,3580.42) 3233.15,3580.53 3233.15,3619.84 U1.1@3233.04,3619.94 3233.04,3664.23 3256.85,3688.04 3256.85,3799.5 R3.2@3256.45,3799.9 C1.1@3256.45,3861.9
  Bottom Layer w8: v1(3233.25,3580.42) 3233.93,3579.74 3233.93,1613.18 v1(3234.61,1612.5)
NetC1_2: C1.2 R3.1 R4.2 U1.4 | length 213.7
  Top Layer w8: C1.2@3319.44,3861.9 R3.1@3319.44,3799.9 3307.85,3788.3 U1.4@3307.85,3728.21 R4.2@3383,3728.21
NetC4_1: C4.1 R9.2 R10.2 U1.3 | length 217.7
  Top Layer w8: U1.3@3307.85,3619.94 3376.08,3619.94 R9.2@3383,3626.87 3383,3554.46 R10.2@3382.44,3553.9 C4.1@3448.95,3553.9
